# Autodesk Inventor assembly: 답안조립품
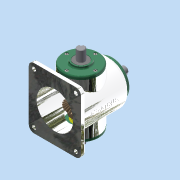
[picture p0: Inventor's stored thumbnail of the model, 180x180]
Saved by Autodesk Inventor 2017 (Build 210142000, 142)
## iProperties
Part Number: 답안조립품
Material: 일반
Document SubType Name: Assembly
Designer: MRC
Author: MRC
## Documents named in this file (16)
- C:\Users\MRC\Desktop\710116V1004\답안조립품.iam
- C:\Users\MRC\Desktop\710116V1004\Ű 4x4.ipt
- C:\Users\MRC\Desktop\710116V1004\Ű 5x5.ipt
- C:\Users\MRC\Desktop\710116V1004\메인 베벨기어.ipt
- C:\Users\MRC\Desktop\710116V1004\메인 축.ipt
- 메인 축.ipt
- C:\Users\MRC\Desktop\710116V1004\베어링 6203.ipt
- C:\Users\MRC\Desktop\710116V1004\본체.ipt
- C:\Users\MRC\Desktop\710116V1004\볼트 M4.ipt
- 볼트 M4.ipt
- C:\Users\MRC\Desktop\710116V1004\서브 베벨기어.ipt
- C:\Users\MRC\Desktop\710116V1004\서브 축.ipt
- 서브 축.ipt
- C:\Users\MRC\Desktop\710116V1004\오일 실.ipt
- 오일 실.ipt
- C:\Users\MRC\Desktop\710116V1004\커버.ipt
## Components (3 placed, 2 different names)
1. Ű 4x4:1
2. Ű 5x5:1
3. Ű 5x5:2
